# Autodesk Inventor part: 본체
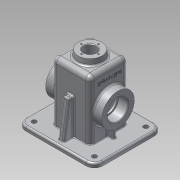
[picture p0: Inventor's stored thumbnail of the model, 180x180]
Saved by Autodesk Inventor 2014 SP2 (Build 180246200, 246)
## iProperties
Created: 2016-08
Part Number: 본체
Material: 알루미늄 6061
Document SubType Name: Modeling
Designer: user
Density: 2.71 g/cm^3
Appearance: 알루미늄 - 평지
Mass: 800.378 g
Surface Area: 913.135 cm^2
Volume: 295.343 cm^3
Author: user
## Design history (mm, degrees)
sketch "스케치1"
  geometry: L1 (65, -57.5)-(-65, -57.5); L2 (-65, -57.5)-(-65, 57.5); L3 (-65, 57.5)-(65, 57.5); L4 (65, 57.5)-(65, -57.5); L5 (65, -57.5)-(-65, 57.5); L6 (-65, -57.5)-(65, 57.5); 1 further point
  constraints: 12 end point, 2 midpoint, 2 parallel, 1 horizontal, 1 perpendicular
  dimensions: "d0" = 130 distance of L2.end L3.end; "d1" = 115 distance of L1.end L2.end
extrude "돌출1" new body sketch "스케치1" distance "d2" = 7; taper "d3" = 0 deg
fillet "모깎기1" dims "d4" = 14
sketch "스케치2"
  geometry: L1 (-65, 43.5)-(-65, -43.5) reference; L2 (-51, -57.5)-(51, -57.5) reference; L3 (65, -43.5)-(65, 43.5) reference; L4 (51, 57.5)-(-51, 57.5) reference; L5 (-60, 43.5)-(-60, -43.5); L6 (-51, -52.5)-(51, -52.5); L7 (60, -43.5)-(60, 43.5); L8 (51, 52.5)-(-51, 52.5); A1 r 14 centre (-51, 43.5) between (-51, 57.5) and (-65, 43.5) reference; A2 r 14 centre (-51, -43.5) between (-65, -43.5) and (-51, -57.5) reference; A3 r 14 centre (51, -43.5) between (51, -57.5) and (65, -43.5) reference; A4 r 14 centre (51, 43.5) between (65, 43.5) and (51, 57.5) reference; A5 r 9 centre (-51, 43.5) between (-51, 52.5) and (-60, 43.5); A6 r 9 centre (-51, -43.5) between (-60, -43.5) and (-51, -52.5); A7 r 9 centre (51, -43.5) between (51, -52.5) and (60, -43.5); A8 r 9 centre (51, 43.5) between (60, 43.5) and (51, 52.5); 1 further point
  constraints: 8 end point, 8 point on circle, 4 centre point, 7 other
  dimensions: "d5" = 5 distance between parallel lines of L8 L4
extrude "돌출2" join sketch "스케치2" distance "d6" = 3; taper "d7" = 0 deg
sketch "스케치3"
  geometry: L1 (32.5, -32.5)-(-32.5, -32.5); L2 (-32.5, -32.5)-(-32.5, 32.5); L3 (-32.5, 32.5)-(32.5, 32.5); L4 (32.5, 32.5)-(32.5, -32.5); L5 (32.5, -32.5)-(-32.5, 32.5); L6 (-32.5, -32.5)-(32.5, 32.5); 1 further point
  constraints: 12 end point, 2 midpoint, 2 parallel, 1 horizontal, 1 perpendicular
  dimensions: "d8" = 65 distance of L2.end L3.end; "d9" = 65 distance of L1.end L2.end
extrude "돌출3" join sketch "스케치3" distance "d10" = 100; taper "d11" = 0 deg
fillet "모깎기2" dims "d12" = 8
fillet "모깎기3" dims "d13" = 8
sketch "스케치4"
  geometry: L1 (32.5, 7)-(32.5, 99) reference; L2 (24.5, 107)-(-24.5, 107) reference; L3 (-32.5, 99)-(-32.5, 7) reference; L4 (-27.5, -3)-(-27.5, 99); L5 (-24.5, 102)-(24.5, 102); L6 (27.5, 99)-(27.5, -3); L7 (51, -3)-(-51, -3) reference; A1 r 8 centre (24.5, 99) between (32.5, 99) and (24.5, 107) reference; A2 r 8 centre (-24.5, 99) between (-24.5, 107) and (-32.5, 99) reference; A3 r 3 centre (-24.5, 99) between (-24.5, 102) and (-27.5, 99); A4 r 3 centre (24.5, 99) between (27.5, 99) and (24.5, 102); 1 further point
  constraints: 6 end point, 4 point on circle, 2 centre point, 2 point on line, 4 other
  dimensions: "d14" = 5 distance between parallel lines of L4 L3
extrude "돌출4" cut sketch "스케치4" stored distance "d15" = 55; taper "d16" = 0 deg
fillet "모깎기4" dims "d17" = 3
node "작업 평면1"
sketch "스케치6"
  geometry: L1 (10, 0)-(10, 49) reference; C1 r 27.5 at (-45, 24.5); 1 further point
  constraints: 1 centre point, 1 horizontal alignment
  dimensions: "d19" = 55 diameter of C1; "d20" = 55 distance from line of L1 C1.centre
extrude "돌출5" join sketch "스케치6" stored distance "d21" = 95; taper "d22" = 0 deg
hole "구멍1" diameter "d25" = 35; stored, may be unused: countersink angle "d29" = 90 deg, drill point angle "d31" = 0 deg; dims "d26" = 6, "d27" = 4, "d28" = 2, "d30" = 17, "d32" = 10, "d33" = 10
sketch "스케치7"
  geometry: C1 r 15 at (0, 0); C2 r 17.5 at (0, 0) reference; 1 further point
  constraints: 1 centre point, 1 concentric
  dimensions: "d34" = 30 diameter of C1
extrude "돌출6" cut sketch "스케치7" distance "d35" = 3; taper "d36" = 0 deg
node "작업 평면3"
sketch "스케치17"
  geometry: C1 r 20 at (0, 0); 1 further point
  constraints: 1 centre point, 1 coincident
  dimensions: "d121" = 40 diameter of C1
extrude "돌출8" join sketch "스케치17" stored distance "d122" = 10; taper "d123" = 7 deg
hole "구멍2" diameter "d42" = 21; stored, may be unused: countersink angle "d46" = 90 deg, drill point angle "d48" = 118 deg; dims "d43" = 6, "d44" = 4, "d45" = 2, "d47" = 8, "d124" = 10, "d125" = 10
sketch "스케치9" dims "d49" = 42
  geometry: C1 r 27.5 at (0, 0) reference; 3 further points
  constraints: 2 vertical alignment, 3 other
hole "구멍3" sketch "스케치9" at (0, 21) diameter "d50" = 3.242; stored, may be unused: countersink angle "d54" = 90 deg, drill point angle "d56" = 118 deg; dims "d51" = 8, "d52" = 4, "d53" = 2, "d55" = 10
sketch "스케치10"
  geometry: L1 (-60, 43.5)-(-60, -43.5) reference; L2 (51, 52.5)-(-51, 52.5) reference; 5 further points
  constraints: 2 horizontal alignment, 2 vertical alignment
  dimensions: "d60" = 102 distance of point (-51, -43.5) point (51, -43.5); "d61" = 87 distance of point (-51, -43.5) point (-51, 43.5); "d62" = 9 distance from line of point (-51, -43.5) L1; "d63" = 9 distance from line of L2 point (-51, 43.5)
hole "구멍4" sketch "스케치10" at (51, -43.5), (-51, -43.5), (-51, 43.5), (51, 43.5) diameter "d64" = 8; stored, may be unused: countersink angle "d68" = 90 deg, drill point angle "d70" = 118 deg; dims "d65" = 8, "d66" = 4, "d67" = 2, "d69" = 10
sketch "스케치13"
  geometry: L1 (-57.5, 7)-(-43.5, 7) reference; L2 (-57.5, 0)-(-57.5, 7) reference; L3 (-49.5, 7)-(-41.068, 67); L4 (-32.5, 7)-(-32.5, 99) reference; L5 (-41.068, 67)-(-32.5, 67); 1 further point
  constraints: 4 end point, 2 point on line, 1 perpendicular
  dimensions: "d71" = 8 distance from line of L2 L3.start; "d72" = 8 deg angle of L2 L3; "d73" = 60 vertical distance of L3.start L3.end
feature "리브1" sketch "스케치13" dims "d74" = 1, "d75" = 10, "d76" = 0, "d77" = 0, "d78" = 1, "d79" = 1
fillet "모깎기5" dims "d80" = 0.3
sketch "스케치18" dims "d126" = 29
  geometry: 3 further points
  constraints: 2 horizontal alignment, 1 coincident, 2 other
hole "구멍6" sketch "스케치18" at (14.5, 0) diameter "d127" = 2.459; stored, may be unused: countersink angle "d131" = 90 deg, drill point angle "d133" = 118 deg; dims "d128" = 7, "d129" = 4, "d130" = 2, "d132" = 9
sketch "스케치15"
  geometry: L1 (32.5, 24.5)-(47.5, 24.5) reference; L2 (-51, 7)-(51, 7) reference; L3 (42.5, 24.5)-(42.5, 7); L4 (27.5, 99)-(27.5, -3) reference; 1 further point
  constraints: 2 end point, 2 point on line, 1 perpendicular
  dimensions: "d92" = 15 distance between parallel lines of L3 L4
feature "리브2" sketch "스케치15" dims "d93" = 1, "d94" = 6, "d95" = 0, "d96" = 0, "d97" = 1, "d98" = 1
chamfer "모따기1" distance "d99" = 1; stored, may be unused: second distance "d100" = 2, angle "d101" = 45 deg
fillet "모깎기6" dims "d102" = 3
fillet "모깎기7" dims "d103" = 3
fillet "모깎기8" dims "d104" = 3
fillet "모깎기9" dims "d105" = 3
fillet "모깎기10" dims "d106" = 3
fillet "모깎기11" dims "d107" = 3
fillet "모깎기12" dims "d108" = 3
fillet "모깎기13" dims "d109" = 3
fillet "모깎기14" dims "d110" = 3
fillet "모깎기15" dims "d111" = 3
fillet "모깎기16" dims "d112" = 3
fillet "모깎기17" dims "d113" = 1
fillet "모깎기18" dims "d114" = 3
node "작업 평면2"
sketch "스케치16"
  geometry: L1 (0, -8)-(91, -8) reference; L2 (-18, 4.5)-(-18, 44.5) reference; 2 further points
  constraints: 1 other
  dimensions: "d116" = 32.5 distance from line of point (8, 24.5) L1; "d137" = 26 distance from line of L2 point (8, 24.5)
feature "엠보싱1" sketch "스케치16" dims "d118" = 0.5, "d119" = 0
fillet "모깎기19" dims "d138" = 3
chamfer "모따기2" distance "d139" = 1; stored, may be unused: second distance "d140" = 2, angle "d141" = 45 deg
node "솔리드1"
mirror "대칭2"
mirror "대칭3"
mirror "대칭4"
pattern_circular "원형 패턴1" dims angle "d58" = 360 deg
mirror "대칭5"
mirror "대칭6"
pattern_circular "원형 패턴3" dims angle "d135" = 360 deg
mirror "대칭7"
other parameters: "d18" = 15, "d115" = 10.5
